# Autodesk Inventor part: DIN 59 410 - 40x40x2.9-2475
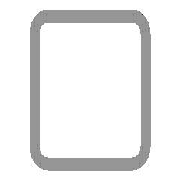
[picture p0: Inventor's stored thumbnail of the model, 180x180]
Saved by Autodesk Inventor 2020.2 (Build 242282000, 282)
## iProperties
Manager: www.cadconsulting.pl
Company: Fabian Stasiak CAD Consulting
_CCFamilyMember: 10
_CCFamilyDisplayName: DIN 59410 (Kwadrat) - Rurki stalowe o przekroju kwadratowym formowane na gorąco
_FrameMemberDoc: Frame Member File
_Version: 15.0.0
_GetPNFromCC: 1
Created: 2014-02
Part Number: DIN 59 410 - 40x40x2.9-2475
Material: Stal, miękka
Description: Rurki stalowe o przekroju kwadratowym formowane na gorąco
Document SubType Name: Modellieren
Standard: DIN
Designer: F.Stasiak
Standards Organization: DIN
Language: pl-PL
Size Designation: 40x40x2.9
Categories: <MemberInstance><Categories><Category DisplayName="Kształtowniki konstrukcyjne" InternalName="089c4875-fa83-4c05-b084-43b9cc11f5ed" Mnemonic="GRDR"><CategoryPar
Stock Number: 40x40x2.9
Density: 7.85 g/cm^3
Appearance: Częściowo polerowana
Mass: 7940.58 g
Surface Area: 6984.3 cm^2
Volume: 1011.54 cm^3
Catalog Web Link: www.expertbooks.pl
IsCustomPart: 1
G_L: 2475,000 mm
G_W: 40,000 mm
G_H: 40,000 mm
+5526C40D-016D-419C-9385-9BFDD53187C0+CUTDETAIL1: Wytnij
Author: F.Stasiak
Subject: Zbiór ćwiczeń. Autodesk Inventor 2020. Kurs Professional
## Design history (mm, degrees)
node "Płaszczyzna początkowa"
node "Płaszczyzna końcowa"
sketch "Szkic"
  geometry: L1 (-14.2, 20)-(14.2, 20); L2 (20, 14.2)-(20, -14.2); L3 (14.2, -20)-(-14.2, -20); L4 (-20, -14.2)-(-20, 14.2); L5 (-29.682, 0)-(29.682, 0) reference; L6 (0, -29.682)-(0, 29.682) reference; L7 (-14.2, 17.1)-(14.2, 17.1); L8 (17.1, 14.2)-(17.1, -14.2); L9 (14.2, -17.1)-(-14.2, -17.1); L10 (-17.1, -14.2)-(-17.1, 14.2); A1 r 5.8 centre (-14.2, 14.2) between (-14.2, 20) and (-20, 14.2); A2 r 5.8 centre (14.2, 14.2) between (20, 14.2) and (14.2, 20); A3 r 5.8 centre (14.2, -14.2) between (14.2, -20) and (20, -14.2); A4 r 5.8 centre (-14.2, -14.2) between (-20, -14.2) and (-14.2, -20); A5 r 2.9 centre (-14.2, 14.2) between (-14.2, 17.1) and (-17.1, 14.2); A6 r 2.9 centre (14.2, 14.2) between (17.1, 14.2) and (14.2, 17.1); A7 r 2.9 centre (14.2, -14.2) between (14.2, -17.1) and (17.1, -14.2); A8 r 2.9 centre (-14.2, -14.2) between (-17.1, -14.2) and (-14.2, -17.1); 3 further points
  constraints: 16 end point, 16 point on circle, 8 centre point, 8 tangent, 6 point on line, 4 parallel, 3 equal radius, 3 perpendicular, 1 horizontal, 7 other
  dimensions: "b" = 40 distance of point (-20, 20) point (20, 20); "msp_r" = 5.8 radius of A1 (= 2 x ParT); "d8" = 20 distance between parallel lines of L4 L6 (= d9); "d9" = 20 distance between parallel lines of L3 L5 (= 0.5 x b); "d10" = 2.9 distance between parallel lines of L3 L9 (= ParT)
extrude "Bryła" new body sketch "Szkic" taper "d4" = 0 deg; stored distance "NLG" = 10
node "Driven Length"
  sketch "Sketch2"
    geometry: L1 (0, 0)-(10, 0) reference
    constraints: 2 end point, 1 horizontal
  workplane "Work Plane3"
  sketch "Sketch3"
    geometry: L1 (-2, 25)-(12, 25) reference; L2 (-2, 2500)-(12, 2500) reference
    dimensions: "d14" = 2475 distance between parallel lines of L1 L2 (derived)
node "Płaszczyzna konstrukcyjna4"
feature "Podział1"
body "Solid1"
other parameters: "ParT" = 2.9, "G_OFFSET_START" = -25 [user parameter; used in 1 equation term], "G_OFFSET_END" = 0 [user parameter; used in 1 equation term], "d11" = 25 (= -G_OFFSET_START), "G_L" = 2475 (= d14) [user parameter], "d13" = 90 deg
